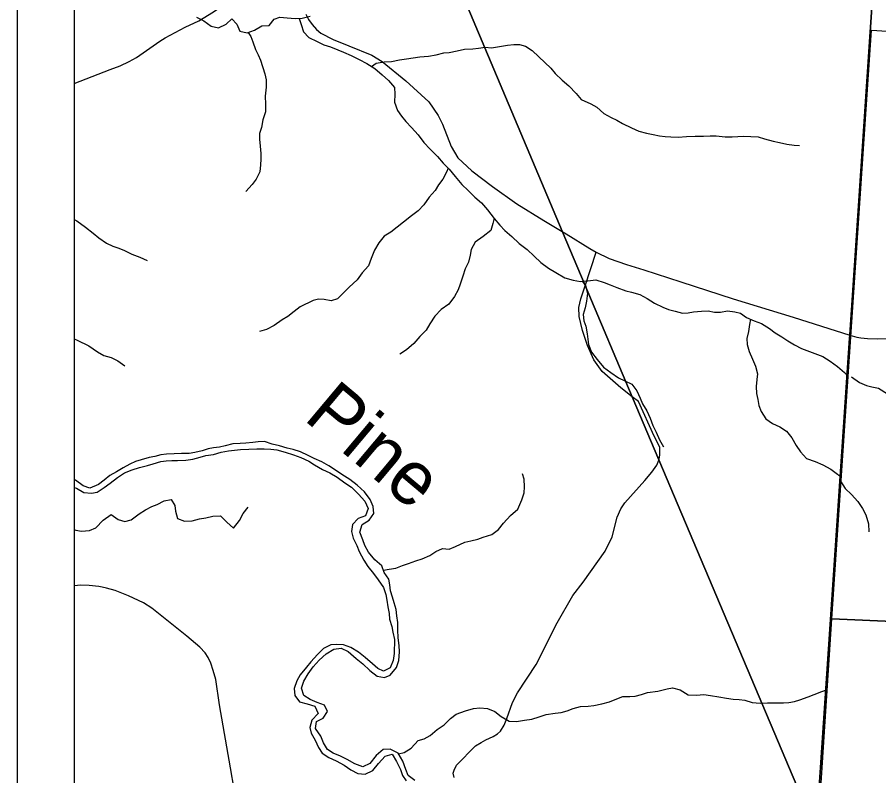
# Model space of a CAD drawing. Extents: x 0 to 34, y 0 to 22.
# Drawn here: x 2 to 3.511, y 18.363 to 19.693 of the extents above; entities that cross this region are included whole.
import ezdxf

# ---------------------------------------------------------------- set-up
doc = ezdxf.new("R2010")
doc.units = 0
for name, color, linetype in [('GM_X_County_Road', 7, 'Continuous'), ('GM_X_Minor_River', 7, 'Continuous'), ('GM_X_Minor_River_Text', 7, 'Continuous'), ('GM_X_Section', 7, 'Continuous'), ('GM_X_State_Route', 7, 'Continuous'), ('GM_X_Township_Road', 7, 'Continuous'), ('GM_X_Unincorporated', 7, 'Continuous'), ('SH_Cut_Line', 7, 'Continuous'), ('SH_Data', 7, 'Continuous')]:
    doc.layers.add(name, color=color, linetype=linetype)

msp = doc.modelspace()

# ---------------------------------------------------------------- linework, layer by layer
at = {"layer": 'GM_X_County_Road'}
msp.add_lwpolyline([(2.1, 19.577), (2.1629, 19.6015), (2.1807, 19.6078), (2.1964, 19.6157), (2.2092, 19.6227), (2.2498, 19.6515), (2.2594, 19.6574), (2.2946, 19.6756), (2.3185, 19.6871), (2.3444, 19.7028), (2.3667, 19.7187), (2.3804, 19.7267), (2.3947, 19.7344), (2.4447, 19.7581), (2.4861, 19.7772)], dxfattribs=at)
at = {"layer": 'GM_X_Minor_River'}
for points in [[(2.3146, 19.6936), (2.3274, 19.687), (2.3398, 19.6778), (2.353, 19.6747), (2.3663, 19.681), (2.3766, 19.6904), (2.3849, 19.6809), (2.3905, 19.6691), (2.4033, 19.666), (2.4162, 19.6708), (2.4292, 19.6783), (2.4416, 19.6789), (2.4508, 19.6899), (2.4607, 19.6936), (2.4732, 19.692), (2.4872, 19.6911), (2.4997, 19.6914), (2.5137, 19.6951)], [(2.4943, 19.6913), (2.4977, 19.6804), (2.5021, 19.6678), (2.5111, 19.6579), (2.5258, 19.651), (2.5379, 19.6448), (2.5492, 19.6413), (2.5624, 19.6363), (2.5722, 19.632), (2.5854, 19.6259), (2.5998, 19.6193), (2.613, 19.612), (2.6273, 19.6032), (2.6397, 19.5921), (2.651, 19.5825), (2.6618, 19.5703), (2.6621, 19.5581), (2.6616, 19.5441), (2.6668, 19.5297), (2.6739, 19.5201), (2.6814, 19.5102), (2.6912, 19.4999), (2.7032, 19.4873), (2.7129, 19.4739), (2.7242, 19.4617), (2.737, 19.4491), (2.7471, 19.4376), (2.7572, 19.427), (2.7681, 19.414), (2.7797, 19.4002), (2.791, 19.3895), (2.8026, 19.3777), (2.8143, 19.3677), (2.8244, 19.3555), (2.8364, 19.3403), (2.8462, 19.3288), (2.8548, 19.3193), (2.8672, 19.3089), (2.88, 19.2967), (2.8939, 19.286), (2.9063, 19.2745), (2.918, 19.263), (2.9315, 19.2534), (2.9447, 19.2454), (2.9605, 19.2361), (2.9749, 19.2322), (2.9877, 19.2299), (3.0006, 19.2313), (3.0146, 19.2327), (3.029, 19.228), (3.0399, 19.2241), (3.0512, 19.2191), (3.0671, 19.2137), (3.0769, 19.2113), (3.0916, 19.2071), (3.1048, 19.2001), (3.1176, 19.1921), (3.132, 19.1847), (3.1418, 19.1809), (3.1535, 19.1777), (3.1667, 19.1746), (3.1765, 19.1749), (3.186, 19.1767), (3.2, 19.1781), (3.2118, 19.1784), (3.2224, 19.1764), (3.233, 19.1764), (3.2455, 19.1782), (3.2583, 19.1769), (3.2681, 19.1742), (3.2787, 19.1669), (3.2923, 19.1611), (3.3051, 19.1565), (3.319, 19.1472), (3.3292, 19.14), (3.3409, 19.1327), (3.351, 19.1258), (3.3627, 19.1188), (3.3755, 19.1123), (3.3891, 19.1069), (3.4125, 19.0984), (3.4253, 19.0903), (3.4385, 19.0811), (3.4505, 19.0704), (3.456, 19.0647)], [(2.4049, 19.6666), (2.4097, 19.6595), (2.4134, 19.65), (2.4179, 19.637), (2.4223, 19.6275), (2.4264, 19.618), (2.4342, 19.5941), (2.4364, 19.5838), (2.4366, 19.5705), (2.435, 19.5546), (2.4356, 19.541), (2.4352, 19.5273), (2.4305, 19.5133), (2.4281, 19.4997), (2.425, 19.4895), (2.4246, 19.4792), (2.426, 19.4671), (2.4274, 19.4542), (2.4273, 19.4443), (2.4265, 19.4345), (2.4252, 19.422), (2.4187, 19.4095), (2.4118, 19.3997), (2.4011, 19.3877)], [(2.6215, 19.6067), (2.6296, 19.613), (2.6436, 19.6148), (2.6561, 19.6158), (2.6702, 19.6184), (2.6827, 19.6202), (2.694, 19.622), (2.7062, 19.6238), (2.7209, 19.6252), (2.7346, 19.6273), (2.7482, 19.6306), (2.7577, 19.6317), (2.7717, 19.6346), (2.7843, 19.6372), (2.799, 19.6378), (2.8089, 19.6389), (2.8206, 19.6407), (2.8316, 19.6395), (2.8494, 19.6424), (2.8596, 19.6446), (2.871, 19.6456), (2.8808, 19.6452), (2.891, 19.6428), (2.9027, 19.6351), (2.9147, 19.624), (2.9249, 19.6141), (2.9358, 19.6041), (2.9433, 19.5946), (2.9553, 19.5831), (2.9673, 19.5728), (2.9801, 19.5594), (2.9891, 19.5491), (3.0057, 19.5414), (3.0166, 19.5353), (3.0286, 19.5245), (3.0415, 19.5176), (3.0513, 19.5126), (3.0614, 19.5068), (3.0769, 19.4991), (3.0897, 19.4937), (3.1037, 19.4898), (3.115, 19.4875), (3.1264, 19.4855), (3.1362, 19.4839), (3.146, 19.4834), (3.1589, 19.4829), (3.1737, 19.484), (3.1888, 19.4846), (3.2032, 19.4845), (3.2153, 19.4852), (3.2255, 19.4855), (3.2414, 19.4838), (3.2539, 19.4833), (3.2638, 19.4844), (3.2736, 19.4847), (3.2865, 19.4842), (3.299, 19.4834), (3.3103, 19.4799), (3.3258, 19.4759), (3.3364, 19.4736), (3.3496, 19.4708), (3.3621, 19.4688), (3.3719, 19.4684)], [(2.7557, 19.4285), (2.7527, 19.4217), (2.7465, 19.4092), (2.7389, 19.3994), (2.7331, 19.3896), (2.7224, 19.3776), (2.7132, 19.3644), (2.7033, 19.3538), (2.6915, 19.3448), (2.6774, 19.3339), (2.6663, 19.3253), (2.6549, 19.3163), (2.6435, 19.3095), (2.634, 19.2979), (2.6263, 19.2846), (2.6209, 19.2703), (2.6159, 19.2574), (2.6048, 19.245), (2.596, 19.2329), (2.5822, 19.2198), (2.5616, 19.1995), (2.5506, 19.1961), (2.5382, 19.1985), (2.5283, 19.199), (2.5188, 19.1964), (2.496, 19.1852), (2.4858, 19.1773), (2.4747, 19.1687), (2.4645, 19.1627), (2.4504, 19.1529), (2.4371, 19.1455), (2.4249, 19.1421)], [(2.1, 19.3389), (2.1047, 19.3365), (2.1198, 19.325), (2.1333, 19.3147), (2.1431, 19.3066), (2.1563, 19.2974), (2.1676, 19.2917), (2.1781, 19.2885), (2.1883, 19.2843), (2.2012, 19.2777), (2.2151, 19.2727), (2.2276, 19.2669)], [(2.8361, 19.3407), (2.8341, 19.3316), (2.8302, 19.3191), (2.8169, 19.3089), (2.8028, 19.2988), (2.7959, 19.286), (2.7943, 19.2761), (2.7912, 19.264), (2.7854, 19.2519), (2.7815, 19.2391), (2.7768, 19.2251), (2.773, 19.2152), (2.7665, 19.2035), (2.7569, 19.19), (2.7436, 19.1806), (2.7321, 19.1689), (2.7237, 19.1557), (2.7168, 19.1448), (2.7061, 19.1335), (2.6954, 19.1211), (2.6824, 19.1098), (2.6707, 19.1027)], [(2.9908, 19.2302), (2.9964, 19.223), (3, 19.2093), (2.998, 19.1953), (2.9961, 19.1839), (2.9926, 19.1722), (2.9936, 19.1612), (2.9969, 19.1513), (2.9995, 19.1384), (3.0005, 19.1289), (3.002, 19.1194), (3.0068, 19.1057), (3.0169, 19.0931), (3.0278, 19.0798), (3.041, 19.0702), (3.0545, 19.061), (3.0655, 19.056), (3.0775, 19.0498), (3.0865, 19.038), (3.0921, 19.0254), (3.0962, 19.0155), (3.104, 19.003), (3.1096, 18.9904), (3.1148, 18.9775), (3.1204, 18.9657), (3.1263, 18.952), (3.1331, 18.9402)], [(3.2856, 19.1639), (3.2839, 19.1547), (3.2823, 19.1422), (3.2795, 19.1297), (3.2798, 19.1195), (3.2835, 19.107), (3.2895, 19.0936), (3.2943, 19.0815), (3.298, 19.0678), (3.2967, 19.0583), (3.2959, 19.0458), (3.2962, 19.0333), (3.2984, 19.0227), (3.3005, 19.0124), (3.3046, 19.0018), (3.3125, 18.9888), (3.3241, 18.9811), (3.337, 18.9753), (3.349, 18.9673), (3.3584, 18.9555), (3.3659, 18.9425), (3.3737, 18.9311), (3.3842, 18.9196), (3.3993, 18.9142), (3.4129, 18.9084), (3.4265, 18.9011), (3.4381, 18.8923), (3.444, 18.8868)], [(2.1, 19.1291), (2.105, 19.1272), (2.1253, 19.1168), (2.1408, 19.1065), (2.1521, 19.1003), (2.1649, 19.0964), (2.1762, 19.091), (2.1886, 19.0818)], [(3.463, 19.0629), (3.4767, 19.0528), (3.4893, 19.0476), (3.4988, 19.0451), (3.5102, 19.0429), (3.5263, 19.0332), (3.5392, 19.0253), (3.5493, 19.0118), (3.5567, 18.9913), (3.5598, 18.9773), (3.5622, 18.9644), (3.5651, 18.9493)], [(2.6535, 18.6982), (2.6516, 18.7077), (2.6434, 18.7199), (2.6393, 18.7313), (2.6273, 18.742), (2.6157, 18.755), (2.6097, 18.7672), (2.606, 18.7771), (2.6008, 18.7904), (2.6047, 18.8036), (2.6173, 18.8111), (2.6253, 18.8228), (2.6239, 18.8353), (2.6191, 18.8479), (2.6089, 18.8612), (2.5962, 18.8727), (2.5834, 18.8827), (2.5694, 18.8915), (2.5596, 18.898), (2.5465, 18.9069), (2.534, 18.9134), (2.5205, 18.9196), (2.5099, 18.925), (2.4967, 18.9315), (2.4839, 18.9354), (2.4733, 18.9378), (2.4601, 18.9417), (2.4472, 18.9448), (2.4336, 18.9495), (2.4226, 18.9488), (2.4132, 18.9473), (2.401, 18.9463), (2.3912, 18.9456), (2.3783, 18.945), (2.3647, 18.942), (2.3544, 18.9395), (2.3442, 18.938), (2.3347, 18.9362), (2.3245, 18.9332), (2.3116, 18.9299), (2.3017, 18.9281), (2.2881, 18.9282), (2.2752, 18.9276), (2.2616, 18.9273), (2.2521, 18.9259), (2.2411, 18.9233), (2.2313, 18.9211), (2.2176, 18.9174), (2.2074, 18.9144), (2.1975, 18.9096), (2.1857, 18.9032), (2.1743, 18.8961), (2.1621, 18.8898), (2.1526, 18.8815), (2.1423, 18.874), (2.1275, 18.8677), (2.1158, 18.8716), (2.1023, 18.8815), (2.1, 18.8817)], [(2.1, 18.8689), (2.1037, 18.8675), (2.1165, 18.8598), (2.1301, 18.8589), (2.14, 18.8604), (2.1525, 18.8686), (2.1628, 18.8761), (2.1757, 18.8863), (2.1883, 18.8945), (2.2016, 18.8997), (2.2145, 18.9038), (2.2285, 18.9071), (2.2384, 18.9104), (2.2517, 18.9145), (2.2611, 18.9155), (2.271, 18.9158), (2.2812, 18.9161), (2.2956, 18.9168), (2.3081, 18.9186), (2.321, 18.9219), (2.3305, 18.9245), (2.3441, 18.9266), (2.3578, 18.9307), (2.3707, 18.9329), (2.3809, 18.9343), (2.3915, 18.9354), (2.4063, 18.936), (2.4203, 18.9363), (2.4328, 18.9362), (2.4445, 18.9357), (2.4555, 18.9345), (2.4698, 18.9306), (2.4845, 18.9259), (2.4974, 18.9213), (2.5113, 18.9151), (2.5215, 18.9082), (2.5354, 18.9001), (2.5479, 18.8943), (2.5611, 18.887), (2.5746, 18.8767), (2.5863, 18.869), (2.5987, 18.8572), (2.6096, 18.8446), (2.6155, 18.8316), (2.6105, 18.8191), (2.5976, 18.8143), (2.588, 18.8038), (2.5864, 18.7917), (2.589, 18.7799), (2.5957, 18.7669), (2.5998, 18.7563), (2.608, 18.7414), (2.6147, 18.7304), (2.6248, 18.7178), (2.6327, 18.7067), (2.6421, 18.6934), (2.6461, 18.6808)], [(2.642, 18.7239), (2.6522, 18.7255), (2.6639, 18.7273), (2.6757, 18.7318), (2.6859, 18.7355), (2.6992, 18.7403), (2.7102, 18.7437), (2.7235, 18.7496), (2.7342, 18.7567), (2.7456, 18.762), (2.7577, 18.7607), (2.7687, 18.7652), (2.7846, 18.7727), (2.7953, 18.7752), (2.8074, 18.7778), (2.8173, 18.7815), (2.8324, 18.7863), (2.8439, 18.7953), (2.8527, 18.8062), (2.8649, 18.8194), (2.8778, 18.8307), (2.8848, 18.8469), (2.889, 18.8594), (2.8895, 18.8697), (2.8892, 18.8833), (2.8859, 18.8928)], [(3.4439, 18.8798), (3.452, 18.8669), (3.4631, 18.8564), (3.4739, 18.8444), (3.4823, 18.8319), (3.4878, 18.8206), (3.4928, 18.8051), (3.4934, 18.791)], [(2.1, 18.7948), (2.1027, 18.7939), (2.1129, 18.792), (2.1269, 18.7934), (2.1376, 18.7978), (2.1509, 18.8114), (2.1646, 18.8211), (2.177, 18.8123), (2.1884, 18.8088), (2.1998, 18.8118), (2.2138, 18.8223), (2.2249, 18.8294), (2.2359, 18.8354), (2.2454, 18.8391), (2.2576, 18.8454), (2.2701, 18.8476), (2.2764, 18.8369), (2.2775, 18.8274), (2.2812, 18.8145), (2.2932, 18.8095), (2.3065, 18.8105), (2.3194, 18.8138), (2.3308, 18.8157), (2.3429, 18.8182), (2.3565, 18.8189), (2.3674, 18.8078), (2.3791, 18.7975), (2.3898, 18.8106), (2.3963, 18.8231), (2.4051, 18.8344)], [(2.6973, 18.3551), (2.6856, 18.3639), (2.6812, 18.3742), (2.676, 18.389), (2.6682, 18.4027), (2.6538, 18.4097), (2.6417, 18.4094), (2.6295, 18.3985), (2.6181, 18.3846), (2.6059, 18.379), (2.5919, 18.384), (2.5787, 18.3917), (2.5667, 18.3975), (2.5539, 18.4029), (2.5441, 18.409), (2.537, 18.4208), (2.5325, 18.4326), (2.5228, 18.446), (2.5248, 18.4581), (2.5362, 18.4644), (2.5442, 18.4758), (2.539, 18.4868), (2.5262, 18.4918), (2.5137, 18.4969), (2.5024, 18.5038), (2.4983, 18.5167), (2.5026, 18.5288), (2.5103, 18.542), (2.5187, 18.5544), (2.5294, 18.5657), (2.5416, 18.577), (2.5549, 18.5849), (2.5682, 18.5867), (2.5802, 18.5809), (2.5941, 18.5686), (2.6058, 18.5595), (2.6182, 18.548), (2.6314, 18.538), (2.6442, 18.5356), (2.6537, 18.5397), (2.6648, 18.5533), (2.6691, 18.5654), (2.6703, 18.5806), (2.6697, 18.5919), (2.6682, 18.6052), (2.6676, 18.6189), (2.6673, 18.6321), (2.6659, 18.6439), (2.6645, 18.6545), (2.6612, 18.6663), (2.6578, 18.6766), (2.6545, 18.6876), (2.6535, 18.6982)], [(2.6461, 18.6808), (2.6483, 18.6714), (2.6501, 18.6592), (2.6523, 18.6478), (2.653, 18.6379), (2.6567, 18.625), (2.6589, 18.6148), (2.6618, 18.6019), (2.6608, 18.5776), (2.6592, 18.5655), (2.6538, 18.5523), (2.6424, 18.5467), (2.6326, 18.5513), (2.6228, 18.5593), (2.6101, 18.5708), (2.5984, 18.58), (2.5848, 18.5884), (2.572, 18.5927), (2.5591, 18.5936), (2.5497, 18.5925), (2.5371, 18.5862), (2.5264, 18.5756), (2.515, 18.5632), (2.507, 18.5534), (2.4959, 18.5402), (2.4901, 18.5296), (2.4859, 18.516), (2.4865, 18.5039), (2.4948, 18.4928), (2.5084, 18.4893), (2.5216, 18.485), (2.5275, 18.4721), (2.5165, 18.4604), (2.5129, 18.4476), (2.5155, 18.4381), (2.5226, 18.4255), (2.5282, 18.4126), (2.5345, 18.403), (2.5462, 18.3954), (2.5594, 18.3896), (2.5734, 18.3815), (2.585, 18.3734), (2.5971, 18.3673), (2.6103, 18.366), (2.6233, 18.3724), (2.6336, 18.3848), (2.645, 18.3976), (2.6572, 18.4009), (2.665, 18.3884), (2.6721, 18.3743), (2.6758, 18.3636), (2.6818, 18.3541)], [(2.6688, 18.4016), (2.6784, 18.4042), (2.6909, 18.4117), (2.7032, 18.4252), (2.7134, 18.4282), (2.7241, 18.4338), (2.7362, 18.4443), (2.7488, 18.4525), (2.7595, 18.4638), (2.7694, 18.471), (2.7861, 18.4769), (2.8001, 18.481), (2.8111, 18.4824), (2.8244, 18.4811), (2.8372, 18.4757), (2.8485, 18.4673), (2.8624, 18.4592), (2.8753, 18.4584), (2.8897, 18.4605), (2.9022, 18.4623), (2.9155, 18.4664), (2.9276, 18.4705), (2.9431, 18.473), (2.9537, 18.4741), (2.9644, 18.477), (2.9746, 18.4811), (2.9875, 18.4848), (3.0012, 18.4854), (3.011, 18.4865), (3.0254, 18.4894), (3.0387, 18.4927), (3.0516, 18.4983), (3.0622, 18.5024), (3.074, 18.5019), (3.0838, 18.5026), (3.0944, 18.5059), (3.1054, 18.5093), (3.1232, 18.5118), (3.1395, 18.5154), (3.149, 18.5173), (3.1626, 18.5137), (3.1766, 18.5049), (3.1913, 18.5048), (3.2038, 18.5055), (3.2155, 18.5039), (3.2303, 18.5018), (3.2439, 18.4991), (3.2556, 18.4978), (3.2658, 18.497), (3.2757, 18.4958), (3.2885, 18.4915), (3.3025, 18.4907), (3.3154, 18.4913), (3.3301, 18.4908), (3.3434, 18.4911), (3.3532, 18.4918), (3.3627, 18.4936), (3.3722, 18.4966), (3.387, 18.5017), (3.3972, 18.5058), (3.4109, 18.511), (3.4188, 18.514)]]:
    msp.add_lwpolyline(points, dxfattribs=at)
at = {"layer": 'GM_X_Section'}
for points in [[(3.4977, 19.6708), (4.4823, 19.6076), (4.4314, 18.5943), (3.4282, 18.6383)], [(3.4282, 18.6383), (4.4314, 18.5943), (4.383, 17.5655), (3.6608, 17.6237), (3.615, 17.7371), (3.4191, 18.2301), (3.4042, 18.2698)]]:
    msp.add_lwpolyline(points, close=True, dxfattribs=at)
at = {"layer": 'GM_X_State_Route'}
for points in [[(2.5062, 19.6989), (2.5108, 19.6893), (2.5169, 19.6803), (2.5246, 19.6717), (2.5325, 19.6652), (2.5542, 19.6544), (2.5812, 19.6434), (2.6218, 19.627), (2.6397, 19.6155), (2.6812, 19.582), (2.7218, 19.545), (2.738, 19.5212), (2.7459, 19.5059), (2.7611, 19.4666), (2.7724, 19.4466), (2.7969, 19.4238), (2.8334, 19.3962), (2.8758, 19.3661), (2.9235, 19.3369), (2.9555, 19.3175), (2.9623, 19.3134), (3.0041, 19.2877), (3.015, 19.2814)], [(3.015, 19.2814), (3.0378, 19.2701), (3.0686, 19.2596), (3.0989, 19.2501), (3.1638, 19.2291), (3.2556, 19.1996), (3.3609, 19.1672), (3.4602, 19.1356)], [(3.4602, 19.1356), (3.4723, 19.1325), (3.4795, 19.1313), (3.491, 19.13), (3.5091, 19.1296), (3.5256, 19.1302)]]:
    msp.add_lwpolyline(points, dxfattribs=at)
at = {"layer": 'GM_X_Township_Road'}
for points in [[(3.1171, 18.9587), (3.0895, 19.0195), (3.0783, 19.0274), (3.0584, 19.0433), (3.0256, 19.0723), (3.011, 19.0924), (2.9999, 19.1179), (2.9913, 19.1437), (2.9855, 19.1687), (2.9848, 19.1843), (2.9883, 19.1995), (2.9958, 19.2222), (3.015, 19.2814)], [(3.1003, 18.8812), (3.1128, 18.8953), (3.1215, 18.9077), (3.1252, 18.9168), (3.1257, 18.9182), (3.127, 18.926), (3.1268, 18.9387), (3.1196, 18.9533), (3.1171, 18.9587)], [(2.7663, 18.3601), (2.7647, 18.3677), (2.7664, 18.3733), (2.77, 18.3815), (2.8037, 18.4156), (2.8134, 18.4218), (2.8218, 18.426), (2.8347, 18.4323), (2.8423, 18.4369), (2.8473, 18.4413), (2.8541, 18.4518), (2.8585, 18.4636), (2.8685, 18.4914), (2.8775, 18.5085), (2.9102, 18.5582), (2.9467, 18.6311), (2.9744, 18.6793), (2.9924, 18.7029), (3.0312, 18.7569), (3.043, 18.7823), (3.0519, 18.8166), (3.0585, 18.831), (3.0654, 18.8419), (3.1003, 18.8812)], [(2.3804, 18.3396), (2.3737, 18.377), (2.3549, 18.4876), (2.348, 18.5318), (2.3438, 18.5479), (2.3396, 18.5609), (2.335, 18.5707), (2.3298, 18.5787), (2.3203, 18.5887), (2.2975, 18.6078), (2.236, 18.6572), (2.2217, 18.6664), (2.1951, 18.6785), (2.1719, 18.6878), (2.1564, 18.6922), (2.1491, 18.694), (2.1428, 18.6949), (2.1263, 18.6966), (2.1116, 18.6972), (2.1, 18.6962)]]:
    msp.add_lwpolyline(points, dxfattribs=at)
at = {"layer": 'GM_X_Unincorporated'}
for points in [[(2.2853, 20.9), (2.1, 20.9), (2.1, 14.1), (2.8399, 14.1), (2.9778, 14.1609), (3.8099, 14.5285), (4.2904, 14.7408), (4.3998, 14.7897), (4.802, 14.9692), (4.4847, 15.685), (4.2937, 16.1161), (4.0882, 16.6114), (3.972, 16.8916), (3.7367, 17.4136), (3.709, 17.484), (3.4011, 18.2653), (3.1249, 18.9173), (3.0781, 19.0279), (2.9956, 19.2227), (2.9553, 19.318), (2.7473, 19.8121), (2.418, 20.5866)], [(6.769, 20.9), (2.2853, 20.9), (2.418, 20.5866), (2.7473, 19.8121), (2.9553, 19.318), (2.9956, 19.2227), (3.0781, 19.0279), (3.1249, 18.9173), (3.4011, 18.2653), (3.4595, 19.1305), (3.4599, 19.1361), (3.5099, 19.8769), (3.5456, 20.4047), (3.5457, 20.4056), (3.5462, 20.4144), (3.5651, 20.6937), (3.8602, 20.6728), (4.3099, 20.6409), (6.6484, 20.4847), (6.6568, 20.5136)]]:
    msp.add_lwpolyline(points, close=True, dxfattribs=at)
msp.add_lwpolyline([(3.5456, 20.4047), (3.5099, 19.8769), (3.4599, 19.1361), (3.4595, 19.1305), (3.4011, 18.2653), (3.709, 17.484)], dxfattribs=at)
at = {"layer": 'SH_Cut_Line'}
for points in [[(4.2937, 16.1161), (4.0882, 16.6114), (3.972, 16.8916), (3.7367, 17.4136), (3.709, 17.484), (3.4011, 18.2653), (3.4595, 19.1305), (3.4599, 19.1361), (3.5099, 19.8769), (3.5456, 20.4047), (3.5457, 20.4056), (3.5462, 20.4144), (3.5651, 20.6937), (3.8602, 20.6728), (4.3099, 20.6409), (6.6484, 20.4847), (6.6568, 20.5136), (6.769, 20.9), (2.1, 20.9), (2.1, 14.1)], [(8.9, 14.1), (8.9, 20.9), (6.769, 20.9), (6.6568, 20.5136), (6.6484, 20.4847), (4.3099, 20.6409), (3.8602, 20.6728), (3.5651, 20.6937), (3.5462, 20.4144), (3.5457, 20.4056), (3.5456, 20.4047), (3.5099, 19.8769), (3.4599, 19.1361), (3.4595, 19.1305), (3.4011, 18.2653), (3.709, 17.484), (3.7367, 17.4136), (3.972, 16.8916), (4.0882, 16.6114), (4.2937, 16.1161)]]:
    msp.add_lwpolyline(points, dxfattribs=at)
at = {"layer": 'SH_Data'}
for p, q in [((2, 21), (2, 14)), ((2.1, 20.9), (2.1, 14.1))]:
    msp.add_line(p, q, dxfattribs=at)

# ---------------------------------------------------------------- texts
at = {"layer": 'GM_X_Minor_River_Text'}
msp.add_text('Pine', height=0.09469, rotation=320.0016, dxfattribs=at).set_placement((2.5002, 18.9887))

doc.saveas('drawing.dxf')
